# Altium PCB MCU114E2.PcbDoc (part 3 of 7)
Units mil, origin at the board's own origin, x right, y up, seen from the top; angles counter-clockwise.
Board outline 4153.94 x 2313.28 mil, 8 copper layers (Top Layer, GND 2, Signal Layer 3, Power 4, Power 5, Signal Layer 6, GND 7, Bottom), stack 61.2 mil thick; 444 components, 418 nets, 1811 pads, 981 vias.
Unrouted connection lines stored in the file: 3.
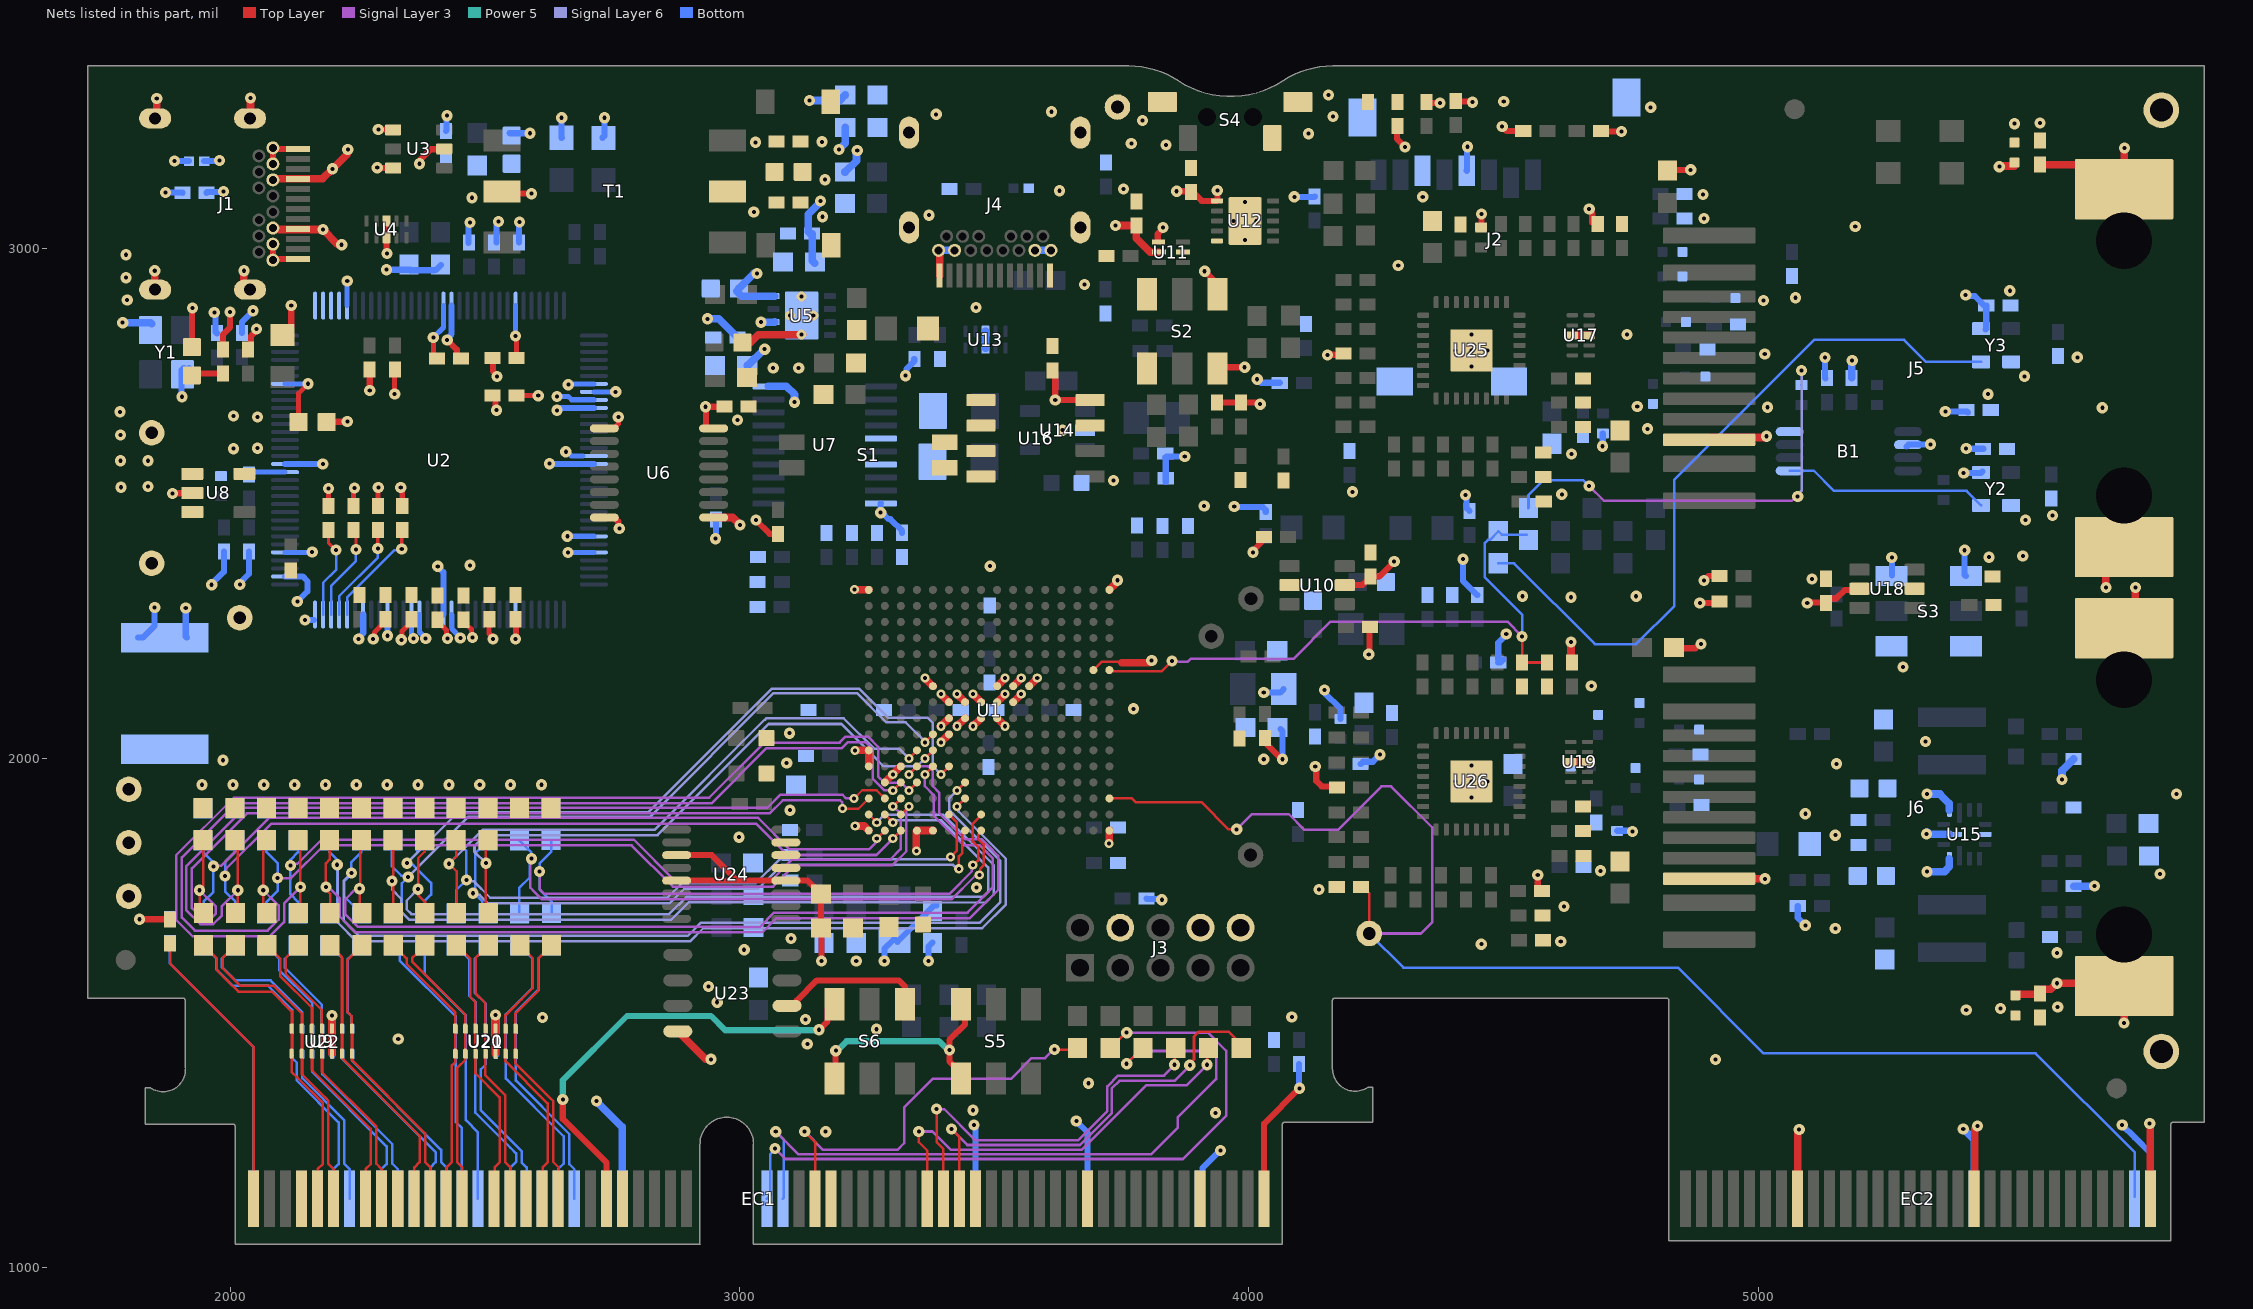
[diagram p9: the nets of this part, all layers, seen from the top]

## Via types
v1: diameter 22, hole 8, Top Layer to Bottom, tented both sides, 810 vias
v2: diameter 18, hole 8, Top Layer to Bottom, tented both sides, 153 vias
v3: diameter 19.68, hole 7.87, Top Layer to Bottom, tented both sides, 10 vias
v4: diameter 19.68, hole 7.87, Top Layer to Bottom, tented bottom, 4 vias
v5: diameter 19.68, hole 7.87, Top Layer to Bottom, tented top, 4 vias

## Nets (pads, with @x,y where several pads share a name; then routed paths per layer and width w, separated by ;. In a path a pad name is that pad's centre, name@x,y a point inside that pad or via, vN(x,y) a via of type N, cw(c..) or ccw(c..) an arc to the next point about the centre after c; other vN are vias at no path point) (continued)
3V3: B1.6 C31.1 C35.1 C36.1 C37.1 C40.2 C43.1 C64.1 C66.1 C86.2 C103.1 C152.1 C153.1 EC1.119 J2.4 J3.10 L3.1 L4.1 R1.2 R2.2 R34.1 R35.1 R36.2 R37.2 R39.2 R40.2 R42.2 R46.1 R51.2 R54.2 R61.2 R71.1 R73.1 R88.2 R89.2 R100.2 R105.2 R106.2 R107.2 R108.1 R111.2 R130.2 R131.1 R133.2 R134.2 R137.2 R138.1 R142.1 R145.2 R151.2 R166.1 R168.2 R202.2 R204.2 R205.1 S2.1 S2.4 S3.1 S3.4 TP5.1 U6.16 U7.20 U10.5 U11.1 U12.1 U16.8 U18.5 Y2.4 Y3.4 | length 3402.1
  Top Layer w12: v1(1822,1684) 1822.06,1683.94 1876.19,1683.94 R204.2@1876.19,1683.88 ; v1(2933.02,2690) C31.1@2969.4,2690 ; v1@2934,2692 2934,2649.29 2935.73,2647.56 U6.16@2949.09,2647.56 ; v1(3032.27,2467.37) 3059.26,2440.38 R100.2@3075,2440.38 ; C86.2@3614,2761.57 3619.6,2755.96 v1(3619.6,2703.23) 3676.33,2703.23 U16.8@3679.87,2699.69 ; U11.1@3820.83,3014.5 3820.83,3029.13 3831,3039.29 v1(3831,3042) ; v1(3858,3113) 3888.38,3113 3907.32,3094.06 U12.1@3937.32,3094.06 3937.83,3094.57 v1(3937.83,3114.27) ; v1(3913,2956) 3937.9,2931.1 S2.1@3937.9,2910.83 ; R54.2@3936.87,2698.31 R51.2@3983.87,2698.31 4018.69,2698.31 v1(4022,2695) v1@4023.31,2696.31 ; S2.4@3937.9,2765.17 3940.23,2767.5 v1(3991.48,2767.5) ; v1(4007.83,2404.27) 4007.83,2407.27 R39.2@4029.25,2428.69 ; EC1.119@4029.8,1135.27 4029.8,1282.8 v1(4099,1352) ; R46.1@4031,2039.38 4031,2031 v1@4062,2000 ; v1(4130,1984) 4131.91,1982.09 4131.91,1955.37 4142.6,1944.68 4172.26,1944.68 R142.1@4172.26,1942.8 ; v1(4153.83,2791.27) 4154.54,2791.98 4183.58,2791.98 R108.1@4184.29,2791.27 ; U10.5@4188.01,2339.69 4221.87,2339.69 C37.1@4238.83,2356.65 4255.65,2356.65 v1(4285,2386) ; v1(4235,2204) 4236.45,2205.45 4236.45,2256.55 R40.2@4237.9,2258 ; C36.1@4290.4,3240.27 4290.4,3215.92 v1(4306.5,3199.82) ; R36.2@4348.51,3288.31 4350.55,3286.27 v1(4374.83,3286.27) ; R37.2@4406.83,3290.27 4408.23,3288.87 4437.77,3288.87 v1(4438.79,3287.85) ; R134.2@4455.83,3041.95 4456.67,3042.8 v1(4456.67,3068.27) ; v1(4497,3240) 4506,3231 R111.2@4538.38,3231 ; v1(4566.87,1770.69) 4566.87,1742.69 R151.2@4571.87,1737.69 ; v1(4667.83,3078.27) 4667.83,3075.56 4673.82,3069.57 4673.82,3051.9 R107.2@4677.83,3047.89 ; R89.2@4690.62,3231 4691.62,3230 v1(4731,3230) ; v1(4885,2305) 4920.57,2305 R138.1@4923.25,2307.69 ; v1(4893.28,2349.13) 4901.62,2357.48 R137.2@4923.6,2357.48 ; v1(5095.87,2304.69) 5096.87,2305.69 C103.1@5131.87,2305.69 ; C103.1@5132.44,2305.06 5132.44,2307.85 5138.25,2313.66 5152.85,2313.66 5169.2,2330.01 5196.2,2330.01 U18.5@5199.87,2333.69
  Bottom w12: v1(1822,1684) 1822.28,1684.28 1881.37,1684.28 R205.1@1881.64,1684.55 ; v1(2953,2431) 2953.56,2431.56 2953.56,2468.4 R1.2@2954.11,2468.95 ; U7.20@3277.24,2499.84 3277.09,2499.84 3277,2499.75 v1(3277,2482) 3279.71,2482 3292.37,2469.34 3296.22,2469.34 3319,2446.56 C35.1@3319,2442.62 ; v1(3284.17,1601.73) 3284.17,1626 3303.17,1645 L4.1@3304,1645 ; L4.1@3309.83,1639.27 3381.33,1710.76 C66.1@3386.53,1710.76 ; v1(3326,2751) 3327.91,2752.91 3327.91,2764.35 3343,2779.44 R71.1@3343,2783.38 ; R202.2@3798.49,1724.69 3799.7,1723.48 3827.62,1723.48 v1(3828.83,1722.27) ; R105.2@3836.62,2542 3836.62,2589 3835.62,2590 3837.82,2592.2 v1(3873.9,2592.2) ; v1(3971.06,2494) 3972.18,2492.88 4027.06,2492.88 4032.87,2487.07 R34.1@4032.87,2483.31 ; v1(4016,2744) 4016.75,2744 4023.75,2737 R88.2@4060.38,2737 ; v1(4029,2129) 4061.19,2129 L3.1@4067.87,2135.69 ; C64.1@4061.48,2057.54 4065.88,2053.14 v1(4065.88,1998) ; v1(4089,3102) 4128.38,3102 R61.2@4129,3102.62 ; R42.2@4098,1399.38 4098.5,1398.88 4098.5,1352.5 v1(4099,1352) ; v1(4148,2134) 4148,2129 4179.99,2097.01 R168.2@4179.99,2077.06 ; R130.2@4218.98,1988.33 4223.82,1993.16 4243.16,1993.16 v1(4257,2007) ; v1(4420.03,2390.69) 4420.03,2348.31 R145.2@4448.03,2320.31 ; v1(4425,2517) 4425,2514.29 4427.06,2512.23 4427.06,2491.12 R35.1@4432.87,2485.31 ; J2.4@4427.45,3153.27 4428.14,3153.96 4428.14,3199.58 v1(4428.83,3200.27) ; R133.2@4489.3,2187.89 4493.24,2187.89 4499.05,2193.7 4489.3,2193.7 4489.3,2226.59 4505,2242.29 v1(4505,2243.65) ; v1(4694.01,2612.38) 4694.42,2612.79 4694.42,2637.17 R131.1@4694.83,2637.58 ; R166.1@4722.83,1857.58 4751.52,1857.58 v1(4752.83,1856.27) ; R2.2@5077.15,1709.69 5077.15,1686.85 v1(5092,1672) ; v1(5130.87,2786.69) 5130.87,2746.69 R73.1@5131.87,2745.69 ; S3.4@5261.83,2358.64 v1(5261.83,2394.27) ; B1.6@5290.87,2611.69 5295.06,2615.87 5337.44,2615.87 v1(5337.83,2616.27) ; v1(5366.87,2680.69) 5408.87,2680.69 C43.1@5410.87,2678.69 ; v1(5402.87,2559.69) 5436.87,2559.69 Y2.4@5439.87,2562.69 ; v1(5404.83,2408.27) 5404.83,2360.02 S3.1@5407.27,2357.58 ; v1(5406.83,2909.27) 5408.74,2907.36 5424.58,2907.36 5443.25,2888.69 C153.1@5447.19,2888.69 ; v1(5407.83,2608.27) 5408.62,2607.48 5441.66,2607.48 C152.1@5441.87,2607.69 ; Y3.4@5445.87,2841.69 5447.19,2843 C153.1@5447.19,2887.69
5V0: C51.1 C53.2 C54.2 R20.1 R21.2 R28.1 R29.1 R53.2 R93.2 R99.2 R103.2 TP9.1 U11.2 U15.7 U15.11 | length 291.7
  Top Layer w15: v1@3738,3045.38 v1(3738,3046) 3738.25,3045.75 C51.1@3778.81,3045.75 3778.81,3020.93 3806.47,2993.27 U11.2@3823.17,2993.27
  Bottom w15: v1(5330.83,1777.27) 5365.27,1777.27 5374.91,1786.91 U15.7@5374.91,1802.95 ; v1(5330.83,1929.69) 5356.31,1929.69 5374.91,1911.09 U15.11@5374.91,1898.42 ; R103.2@5618.62,1749 v1(5659.62,1749)
  other v1: 5820.44,1929.69 3066,2766 3116,2766 3769,3207
20MHZ_CLK: R70.1 Y3.3 | length 1424.1
  Bottom w5.2: R70.1@4489.25,2382.72 4520.28,2382.72 4679,2224 4760,2224 4834.83,2298.83 4834.83,2546.83 5109.27,2821.27 5285.83,2821.27 5328.89,2778.21 Y3.3@5437.07,2778.21
25MHZ_CLK: B1.1 Y2.3 | length 404
  Bottom w5: B1.1@5061.29,2564.3 5108.8,2564.3 5148.33,2524.77 5408.51,2524.77 Y2.3@5437.07,2496.21
ADC_3V0_REF: S6.6 U23.6 | length 291.1
  Top Layer w12: U23.6@3093.28,1514 3106.87,1514 3112.24,1519.37 3112.24,1524.24 3151.84,1563.84 3312.51,1563.84 3324.36,1551.99 S6.6@3324.36,1520.35
ADC_REF: C123.1 R57.2 U24.3 U24.5 U24.12 | length 559.3
  Top Layer w12: U24.5@2876.55,1759.77 2995.83,1759.77 ; U24.3@2876.55,1809.77 2945.83,1809.77 2995.83,1759.77 ; C123.1@3159.5,1668.41 3161,1666.91 v1(3161,1601.73) ; C123.1@3159.98,1668.41 R57.2@3159.98,1722.99 ; R57.2@3162.1,1731.22 3133.55,1759.77 U24.12@3091.11,1759.77 2995.83,1759.77
DEBUG_ID4: R3.1 U2.63 | length 183.1
  Top Layer w6.25: R3.1@2192.85,2448.01 2192.85,2422.89 2207.05,2408.69 v1(2207.87,2408.69)
  Bottom w5: U2.63@2182.5,2282.11 2182.5,2344.5 2207.87,2369.87 v1(2207.87,2408.69)
DEBUG_ID5: R4.1 U2.62 | length 188.2
  Top Layer w6.25: R4.1@2241.87,2448.06 2246.87,2443.06 v1(2246.87,2409.69)
  Bottom w5: U2.62@2198.25,2282.11 2198.25,2338.25 2246.87,2386.87 v1(2246.87,2409.69)
DEBUG_ID6: R5.1 U2.61 | length 197.4
  Top Layer w6.25: v1(2289.87,2411.69) R5.1@2289.87,2448.06
  Bottom w5: U2.61@2214,2282.11 2214,2318 2289.87,2393.87 v1(2289.87,2411.69)
DEBUG_ID7: R6.1 U2.60 | length 217.9
  Top Layer w6.25: v1(2336.87,2410.69) 2336.87,2447.06 R6.1@2337.87,2448.06
  Bottom w5: U2.60@2229.74,2282.11 2229.74,2315.74 2322.7,2408.7 2334.88,2408.7 v1(2336.87,2410.69)
EMU_0: EC1.2 R205.2 | length 567
  Bottom w5: R205.2@1881.64,1637.31 1881.64,1597.36 2046.62,1432.38 EC1.2@2046.62,1138.69
EMU_1: EC1.1 R204.1 | length 566.1
  Top Layer w5: R204.1@1882,1636.63 1882,1597 2046.62,1432.38 2046.62,1282.29 EC1.1@2046.62,1138.69
EMU_3V3: C2.1 C3.1 C4.1 C5.1 C6.1 C7.1 C8.1 C9.1 C18.2 C30.1 R3.2 R4.2 R5.2 R6.2 R7.1 R10.2 R13.2 R14.1 TP2.1 U2.7 U2.8 U2.9 U2.16 U2.26 U2.28 U2.39 U2.47 U2.51 U2.52 U2.69 U2.79 U2.90 U2.101 U2.113 U2.122 U6.1 U8.5 | length 1635.2
  Top Layer w5: U6.1@2733.52,2648.56 U6.1@2734.52,2647.56
  Top Layer w10: C18.2@2134.44,2660 2134.44,2716.41 v1(2153.09,2735.07) ; R3.2@2192.85,2495.26 v1(2192.87,2529.69) ; R4.2@2241.87,2495.31 2241.87,2528.69 v1(2243.87,2530.69) ; v1(2280.83,2234.27) 2283.13,2236.56 2283.13,2246.92 2305.09,2268.89 C7.1@2305.09,2272.82 ; R5.2@2289.87,2495.31 2289.87,2530.69 v1(2290.87,2531.69) ; v1(2323,2715) 2323,2762.06 R7.1@2324,2763.06 ; v1(2334.87,2531.69) 2337.87,2528.69 R6.2@2337.87,2495.31 ; v1(2335.98,2232.42) 2337.13,2233.56 2337.13,2249.33 2349.06,2261.27 2349.48,2261.27 2357.09,2268.89 C6.1@2357.09,2272.82 ; v1(2398.87,2825.69) 2398.87,2792.06 C9.1@2406.25,2784.69 ; C5.1@2408.09,2271.82 2408.09,2267.89 2424.54,2251.44 2424.54,2237.56 v1(2426.83,2235.27) ; C4.1@2459.09,2271.82 2459.09,2267.89 2473.54,2253.44 2473.54,2239.56 v1(2475.83,2237.27) ; C3.1@2508.09,2272.82 2508.09,2244.72 2519.09,2233.72 v1@2519.09,2233.07 ; v1(2559.87,2828.69) 2562.49,2826.06 C8.1@2562.49,2785.69 C8.1@2563.25,2786.44 ; C30.1@2560.87,2711.69 v1(2604.87,2711.69) ; U6.1@2733.52,2648.56 2754.64,2648.56 2762,2655.92 v1(2762,2670)
  Top Layer w12: R14.1@2034.87,2802.31 2040.68,2808.12 2040.68,2828.79 2051.87,2839.98 v1(2051.87,2842.69) ; C2.1@2560.09,2272.82 2561.09,2271.82 v1@2561.09,2234.44
  Bottom w10: R10.2@2036.87,2557.31 2041.2,2561.64 U2.79@2107.7,2561.64 ; U2.69@2107.7,2404.16 2160.18,2404.16 v1(2161.09,2405.07) ; U2.90@2107.7,2734.86 2107.8,2734.97 2152.99,2734.97 v1(2153.09,2735.07) ; U2.101@2229.74,2888.41 2229.74,2936.56 v1(2229.87,2936.69) ; U2.52@2355.73,2282.11 2355.73,2239.37 v1(2359.83,2235.27) ; U2.51@2371.48,2282.11 2371.48,2247.62 v1(2383.83,2235.27) ; v1@2397.87,2824.69 v1(2398.87,2825.69) 2418.72,2845.53 U2.113@2418.72,2888.41 ; U2.47@2434.47,2282.11 2435.53,2281.05 2435.53,2253.46 2451.83,2237.16 v1(2451.83,2236.27) ; v1(2559.87,2828.69) 2560.45,2829.27 U2.122@2560.45,2888.41 ; v1@2560.09,2233.07 2560.45,2233.42 U2.39@2560.45,2282.11 ; v1(2641.85,2710.32) 2663.7,2710.32 2670.4,2703.62 2714,2703.62 U2.9@2714,2703.37 ; v1(2658.87,2601.69) 2661.58,2601.69 2669.94,2593.32 U2.16@2692.44,2593.32 ; v1(2661.87,2435.69) U2.26@2713.98,2435.67 ; v1(2663,2404) 2663.08,2404.08 2713.92,2404.08 U2.28@2714,2404.16 ; v1(2663.83,2733.27) 2665.43,2734.86 U2.7@2714,2734.86 ; U2.8@2714,2719.12 2714.07,2719.19 2756.76,2719.19 v1(2756.83,2719.27)
  other v1: 2516.09,2234.07 2560.09,2234.07 2006.87,2607.69 2053.87,2608.69 2053.87,2669.69 2006.87,2671.69
EMU_5V0: C16.1 C17.2 C20.1 C21.1 C22.1 J1.A4 J1.A9 J1.B4 J1.B9 R15.2 R18.2 T1.5 TP1.1 U3.2 U8.1 U8.3 | length 577.7
  Top Layer w12: TP1.1@1845.87,2638.69 TP1.1@1848.81,2641.62 ; C17.2@1929.81,2759.13 1929.81,2755.06 C16.1@1985.87,2755.06 ; v1(2201,3157) v1@2202,3158 ; v1@2368.86,3170.17 2372,3170.17 2373.36,3171.53 2373.36,3174.67 2394.08,3195.39 2419.61,3195.39 U3.2@2420.29,3196.07 ; T1.5@2533.61,3112.69 2538.03,3108.27 v1(2591.83,3108.27)
  Top Layer w15: J1.B4@2083.93,3040.76 2086.53,3038.16 2096.14,3038.16 2096.29,3038 v1(2182,3038) 2210.66,3009.34 2217.66,3009.34 v1(2219,3008) ; J1.B9@2083.93,3135.24 2085.9,3137.21 J1.A4@2133.54,3137.21 2181.21,3137.21 v1(2201,3157) ; v1@2202,3158 2229.66,3185.66 2229.66,3193.66 v1(2231,3195)
  Bottom w12: C20.1@1949.09,3172.07 1949.7,3172.67 1978.23,3172.67 v1(1978.83,3173.27) ; R15.2@1953.72,3110.07 1954.82,3111.17 1985.73,3111.17 v1(1986.83,3112.27)
  other v1: 1786,2532 1838.87,2533.35 1784.87,2584.02 1838.87,2584.02 1784.87,2634.69 1784,2680 1797.83,2899.27 1795.83,2943.27 1795.83,2988.27 2474.83,3100.27 2371.45,3166.91
EMU_GND: C1.2 C2.2 C3.2 C4.2 C5.2 C6.2 C7.2 C8.2 C9.2 C10.2 C11.2 C12.2 C13.2 C14.2 C15.2 C16.2 C17.1 C18.1 C19.2 C20.2 C21.2 C22.2 C30.2 C34.2 D1.1 D5.2 D6.2 J1.A1 J1.A12 J1.B1 J1.B12 J1.M1 J1.M2 J1.S1 J1.S2 J1.S3 J1.S4 R11.1 R12.1 R15.1 R16.1 R17.2 TP3.1 U2.10 U2.17 U2.48 U2.55 U2.58 U2.64 U2.66 U2.80 U2.114 U3.4 U3.6 U4.3@2306.85,3021.82 U4.8@2306.85,3054.7 U6.8 U8.2 Y1.2 Y1.4 | length 2560.7
  Top Layer w12: v1(1886.87,2519.69) 1887.37,2520.19 1925.37,2520.19 U8.2@1926.87,2521.69 ; C17.1@1924.81,2810.79 1924.81,2878.67 v1@1926.13,2879.99 ; C16.2@1985.87,2802.31 1985.87,2831.69 2000,2845.81 v1(2000,2876) ; J1.M1@2083.93,3009.26 J1.B1@2083.93,2977.76 2085.9,2979.73 J1.A12@2133.54,2979.73 ; J1.M2@2083.93,3166.74 J1.B12@2083.93,3198.24 2085.9,3196.27 J1.A1@2133.54,3196.27 ; D1.1@2102.87,2831.02 2104.35,2831.02 2120,2846.68 v1(2120,2889) ; C18.1@2189.56,2660 2190.06,2660.5 2229.5,2660.5 v1(2230,2661) ; v1@2273.87,2722.13 v1(2274,2722) 2274,2762.94 C1.2@2273.87,2763.06 ; v1(2288.83,3159.27) 2289.13,3158.97 2319.6,3158.97 U3.6@2319.9,3158.66 ; v1(2290.83,3234.27) 2291.23,3233.87 2319.5,3233.87 U3.4@2319.9,3233.47 ; U4.8@2306.85,3054.7 U4.3@2306.85,3021.82 2306.85,2992.31 v1(2308.09,2991.07) ; v1(2426,2821) 2445.15,2801.85 2445.15,2790.5 2450.97,2784.69 C9.2@2453.49,2784.69 ; C30.2@2515.25,2713.69 2520.92,2708.02 2520.92,2685.18 v1(2522.83,2683.27) ; C8.2@2515.25,2785.69 2515.87,2785.06 2515.87,2759.93 2523.83,2751.97 v1(2523.83,2749.27) ; U6.8@2734.52,2472.56 2754.18,2472.56 2762.09,2464.65 2762.09,2452.91 v1(2764,2451)
  Top Layer w15: v1(1852,2957) 1852,2920.72 J1.S3@1852.83,2919.89 ; J1.S2@1852.83,3256.11 1856,3259.28 v1(1856,3295) ; v1(2027,2957) 2027,2931.94 J1.S4@2039.05,2919.89 ; J1.S1@2039.05,3256.11 2040,3257.06 v1(2040,3296)
  Bottom w12: C34.2@1818.87,2236.69 1828.87,2236.69 1851.87,2259.69 v1(1851.87,2295.69) ; v1(1872.83,3110.27) 1872.93,3110.17 1906.37,3110.17 R15.1@1906.47,3110.07 ; v1(1890.83,3172.27) 1890.93,3172.17 1919.19,3172.17 C20.2@1919.29,3172.07 ; v1@1904.64,2719.27 1904.64,2762.08 Y1.4@1908.83,2766.27 ; v1(1912.87,2294.69) 1912.87,2238.69 C34.2@1914.87,2236.69 ; Y1.4@1914.04,2761.05 Y1.4@1919.37,2766.38 ; v1(1963.82,2340.57) 1963.82,2342.07 1987.82,2366.07 C15.2@1987.82,2405.95 ; v1(1969,2875) 1970.91,2873.09 1970.91,2837.27 C14.2@1973.87,2834.31 ; v1(2019.05,2341.23) 2019.05,2343.93 2037.05,2361.93 R11.1@2037.05,2405.98 ; C13.2@2023,2834.62 2023,2856.19 v1(2045.13,2878.31) ; U2.66@2107.7,2356.91 2142.19,2356.91 2151.83,2347.27 2151.83,2327.64 v1(2131.87,2307.69) ; U2.80@2107.7,2577.38 2181.57,2577.38 v1(2181.87,2577.69) ; v1(2146.83,2271.27) U2.64@2164.69,2271.27 ; v1(2252.33,2234.07) 2252.33,2236.88 2261.24,2245.78 U2.58@2261.24,2282.11 ; v1(2307,2959) R16.1@2354.09,2959 ; U2.55@2308.48,2282.11 2308.66,2281.94 v1(2308.66,2240.44) ; R16.1@2353.09,2958 R17.2@2400.5,2958 ; R16.1@2353.09,2958.07 2403.59,2958.07 R17.2@2414.09,2968.57 ; v1(2407.53,2376.69) 2418.72,2365.5 U2.48@2418.72,2282.11 ; C22.2@2423.63,3231.17 2424.73,3232.28 2424.73,3260.17 v1(2425.83,3261.27) ; v1(2426,2821) 2426,2823.71 2434.73,2832.44 2434.73,2888.14 U2.114@2434.47,2888.41 ; C11.2@2468.09,3011.69 2468.09,3048.91 v1(2470.87,3051.69) ; C12.2@2523.02,3012.62 2523.02,3049.84 v1(2526.8,3053.62) ; C21.2@2548.76,3227.44 2549.43,3226.77 v1(2588.5,3226.77) ; C10.2@2567,3012.62 2567,3051.84 v1(2567.78,3052.62) ; v1(2626.83,2578.27) 2627.27,2577.83 2713.55,2577.83 U2.17@2714,2577.38 ; v1(2641.35,2683) 2642.71,2683 2647.33,2687.62 U2.10@2714,2687.62 ; D5.2@2650.87,3218.02 2650.83,3218.07 v1(2650.83,3257.27) ; D6.2@2730.87,3218.02 2734.83,3221.98 v1(2734.83,3257.27)
  Bottom w15: v1(1789,2855) 1843.72,2855 Y1.2@1845.84,2852.88
  other v1: 2470.87,2378.69 1905.27,2709.64 1926.13,2883.99
ERRORSTS: EC2.178 R38.2 TP11.1 U1.P16 | length 2942.4
  Top Layer w5: U1.P16@3726.04,1921.06 3770.21,1921.06 3777.34,1913.94 3878.79,1913.94 3878.96,1913.77 3906.48,1913.77 3959.74,1860.52 v1(3975.88,1860.52) ; R38.2@4218.95,1752.27 4218.95,1751.76 4232.75,1737.96 4233.07,1737.96 4236,1735.03 TP11.1@4236,1656
  Signal Layer 3 w5: v1(3975.88,1860.52) 4005.63,1890.27 4078.04,1890.27 4108.3,1860 4175.29,1860 4260.06,1944.77 4279.08,1944.77 4359.3,1864.55 4359.3,1677.73 4337.56,1656 TP11.1@4236,1656
  Bottom w5: TP11.1@4236,1656 4303,1589 4842.01,1589 5010.25,1420.77 5544.23,1420.77 5739.14,1225.86 EC2.178@5739.14,1138.98
ETH1_EARTH: C101.2 C117.2 J5.10 J5.13 J5.14 J6.10 J6.13 J6.14 pad.6 R136.2 R170.2 | length 938.3
  Top Layer w15: J6.10@4903.31,1763.48 5012.62,1763.48 v1(5012.83,1763.27) ; J5.10@4903.31,2625.13 4907.81,2629.64 5011.75,2629.64 5014.11,2632 v1(5016,2632) ; v1(5472.83,3161.27) 5474.17,3162.61 5501.98,3162.61 C101.2@5504.44,3165.06 ; C117.2@5504.44,1534.69 5506.4,1536.65 5550.47,1536.65 R170.2@5552.44,1538.62 5552.44,1542.56 5556.75,1546.87 5573.54,1546.87 v1@5584.94,1558.27 ; R136.2@5552.44,3165.06 J5.13@5669.68,3165.06 ; v1(5585.83,1558.27) v1@5584.94,1558.27 ; v1(5682,2335) 5682,2378.63 J5.14@5717.87,2414.5 ; v1(5717.83,1480.27) 5717.83,1548.07 5707.64,1558.27 v1@5584.94,1558.27 ; J6.13@5717.87,2255.21 5740,2277.34 v1(5740,2335) ; J5.13@5717.87,3116.87 5718.44,3117.43 v1(5718.44,3197.69)
F28P65x_25MHZ_CLK: R65.2 R75.2 | length 865.8
  Signal Layer 3 w5: v1(4667.83,2534.27) 4696.65,2505.45 5065.57,2505.45 5074.12,2514 v1(5077,2514)
  Signal Layer 6 w5: v1(5077,2514) 5077,2517.6 5084.83,2525.43 v1(5084.83,2761.27)
  Bottom w5.2: R75.2@4548.44,2491.17 4548.56,2491.29 4548.56,2516.56 4578,2546 4656.1,2546 v1(4667.83,2534.27) ; R65.2@5084.44,2732.53 5084.83,2732.92 v1(5084.83,2761.27)
F28P65x_CLK: C126.2 R41.2 R70.2 R75.1 U1.F16 | length 1274
  Top Layer w5: U1.F16@3726.04,2173.03 3728.1,2170.97 3828.97,2170.97 v1(3849,2191) ; v1(4536,2239) C126.2@4536,2187.62 4536.27,2187.89 R41.2@4585,2187.89
  Signal Layer 3 w5: v1(3849,2191) 3850.23,2189.77 3880.08,2189.77 3885.48,2195.17 4087.25,2195.17 4160.09,2268 4507,2268 v1(4536,2239)
  Bottom w5: v1(4536,2239) 4536,2282 4463.05,2354.95 4463.05,2422.67 4468.91,2428.53 4473.05,2428.53 4489.25,2444.73 R70.2@4489.25,2445.72 4496.2,2438.77 R75.1@4545.62,2438.77
GND: B1.4 C23.2 C24.1 C25.2 C26.1 C27.2 C28.1 C29.2 C31.2 C32.2 C33.2 C34.1 C35.2 C36.2 C37.2 C38.2 C39.2 C40.1 C41.1 C42.1 C43.2 C44.2 C45.1 C46.2 C47.2 C49.2 C51.2 C52.1 C53.1 C54.1 C55.2 C56.2 C57.2 C58.2 C59.2 C60.2 C61.2 C62.2 C63.1 C64.2 C65.2 C66.2 C67.2 C68.2 C69.2 C70.2 C71.2 C72.2 C73.2 C74.2 C75.2 C76.2 C77.2 C78.2 C79.2 C80.2 C81.2 C82.2 C83.2 C84.1 C85.1 C86.1 C87.1 C88.1 C89.2 C90.2 C91.2 C92.2 C93.2 C94.2 C95.1 C96.1 C97.2 C98.2 C99.2 C100.2 C101.1 C102.1 C103.2 C104.1 C105.2 C106.2 C107.2 C108.2 C109.2 C110.2 C111.1 C112.1 C113.2 C114.1 C115.2 C116.1 C117.1 C118.1 C119.1 C120.2 C121.2 C122.2 C123.2 C124.2 C125.2 C126.1 C128.2 C129.2 C130.2 C131.2 C132.2 C133.2 C134.2 C135.2 C136.2 C137.2 C138.2 C139.2 C140.2 C141.2 C142.2 C143.2 C144.2 C145.2 C146.2 C147.2 C148.2 C149.2 C150.2 C151.2 C152.2 C153.2 D2.1 D7.1 EC1.7 EC1.10 EC1.19 EC1.22 EC1.35 EC1.38 EC1.46 EC1.47 EC1.65 EC1.83 EC1.97 EC1.111 EC2.135 EC2.157 EC2.179 J2.6 J2.S1 J2.S2 J2.S3 J2.S4 J3.4 J3.8 J4.A1 J4.A12 J4.B1 J4.B12 J4.M1 J4.M2 J4.S1 J4.S2 J4.S3 J4.S4 R22.1 R23.1 R25.1 R26.1 R27.1 R31.1 R32.2 R38.1 R41.1 R43.1 R48.1 R69.2 R72.1 R74.2 R76.2 R77.1 R95.1 R104.1 R109.1 R112.1 R113.1 R123.1 R124.1 R125.1 R127.1 R128.1 R129.1 R132.1 R135.1 R136.1 R139.2 R140.2 R141.2 R143.1 R146.1 R147.1 R159.1 R160.1 R161.1 R162.1 R163.2 R167.1 R169.1 R170.1 R171.1 R206.1 S1.3 S1.4 S2.3 S2.6 S3.3 S3.6 S4.1 S4.2 S4.3 T1.2 TP8.1 U1.A1 U1.A16 U1.F15 U1.G5 U1.G9 U1.G10 U1.G11 U1.H6 U1.H7 U1.H8 U1.H9 U1.H10 U1.J6 U1.J7 U1.J8 U1.J9 U1.K6 U1.L1 U1.M1 U1.M3 U1.N2 U1.T1 U1.T4 U1.T5 U1.T16 U5.5 U5.9@3122,2868.8 U6.9 U7.10 U7.15 U7.17 U9.5 U9.10 U10.2 U11.5 U12.5 U12.11 U13.3@3482.69,2805.13 U13.8@3482.69,2838 U14.2 U15.2 U15.9 U16.1 U16.2 U16.3 U16.4 U16.7 U17.3@4634.86,2830.21 U17.8@4667.74,2830.21 U18.2 U19.3@4631.55,1992.82 U19.8@4664.42,1992.82 U20.5 U20.10 U21.5 U21.10 U22.5 U22.10 U23.4 U24.13 U24.14 U24.15 U25.33 U26.33 Y2.2 Y3.2 | length 2327.2
  Top Layer w5: U1.F15@3694.54,2173.03 3710.52,2189 3750.17,2189 3751.63,2190.46
  Top Layer w12: R135.1@4821.39,3153.32 4823.07,3155 v1(4867,3155) ; R169.1@4834.33,2217.27 4835.6,2216 4876.29,2216 4884.29,2224 v1(4887,2224)
  Top Layer w15: U9.5@2199.56,1420.08 U9.10@2199.56,1469.29 ; U9.10@2200,1469.29 v1(2200,1495) ; U20.5@2520.56,1420.08 2520.56,1453 2521,1453.44 v1(2521,1496) ; U23.4@2878.72,1464 2933.72,1409 v1(2944,1409) ; U6.9@2949.09,2472.56 2986.44,2472.56 v1(3001,2458) ; C26.1@3014.5,2809 3037.09,2831.6 v5@3124,2831.6 ; v2(3225.5,2330.98) 3225.83,2330.65 3253.46,2330.65 U1.A1@3253.6,2330.51 ; v2(3226.84,2015.32) 3227.07,2015.55 U1.L1@3253.6,2015.55 U1.M1@3253.6,1984.05 ; v2(3227,1867) 3244.66,1867 U1.T1@3253.6,1858.07 ; U1.N2@3285.09,1952.55 v2(3300.84,1968.3) U1.M3@3316.59,1984.05 ; v2(3347,1818) 3347,1856.98 U1.T4@3348.09,1858.07 U1.T5@3379.58,1858.07 ; v2(3363.83,2157.28) U1.G5@3379.58,2141.53 ; J4.B1@3390.76,2997.07 3392.73,2995.1 J4.A12@3392.73,2947.46 ; v2@3394.16,2062.6 3395.14,2062.6 U1.J6@3411.08,2078.54 ; v2(3395.33,2031.29) U1.K6@3411.08,2047.04 ; v2(3395.33,2125.78) U1.H6@3411.08,2110.03 ; v2@3425.65,2062.6 3426.63,2062.6 U1.J7@3442.57,2078.54 ; v2(3426.83,2125.78) U1.H7@3442.57,2110.03 ; v2@3457.15,2062.6 3458.13,2062.6 U1.J8@3474.07,2078.54 ; v2(3458.32,2125.78) U1.H8@3474.07,2110.03 ; U1.J9@3505.57,2078.54 v2(3521.31,2062.79) ; U1.H9@3505.57,2110.03 v2(3521.31,2125.78) ; U1.G9@3505.57,2141.53 v2(3521.31,2157.28) ; U1.H10@3537.06,2110.03 v2(3552.81,2125.78) ; U1.G10@3537.06,2141.53 v2(3552.81,2157.28) ; U1.G11@3568.56,2141.53 v2(3584.31,2157.28) ; v2(3725.44,1832.95) 3725.44,1857.47 U1.T16@3726.04,1858.07 ; U1.A16@3726.04,2330.51 3726.04,2330.71 3740.32,2344.99 3740.32,2348.06 v1(3741.66,2349.39) ; 3750.17,2187.67 3804.67,2187.67 v1(3809,2192) ; U19.3@4631.55,1992.82 U19.8@4664.42,1992.82 ; v1(4632,2228) 4632,2189.72 R143.1@4633.83,2187.89 ; U17.3@4634.86,2830.21 U17.8@4667.74,2830.21 ; EC2.135@5076.95,1135.27 5076.95,1267.95 v1(5080,1271) ; EC2.157@5423.41,1135.27 5424.54,1136.4 5424.54,1272.54 v1(5430,1278) ; v1(5768,1283) 5768.93,1282.07 5768.93,1136.2 EC2.179@5769.87,1135.27
  Bottom w12: v1@3371,1600 3371,1630.5 C66.2@3379,1638.5
  Bottom w15: v1(2200,1495) 2200,1444.24 2200.62,1443.62 U22.10@2200.62,1419.01 ; v1(2521,1496) 2521,1444.24 2521.62,1443.62 U21.10@2521.62,1419.01 ; U7.10@3056.76,2730.16 3091.84,2730.16 3107.9,2714.1 v1(3107.9,2699) ; J4.B1@3390.76,2997.07 J4.M1@3422.26,2997.07 ; U13.3@3482.69,2805.13 U13.8@3482.69,2838 ; J4.M2@3579.74,2997.07 J4.B12@3611.24,2997.07 ; R74.2@5183,2746.62 5183,2780 v1(5184,2781) ; v1@5330,1855 5331.89,1855 5336.21,1850.69 U15.9@5375.4,1850.69 ; v1(5596,1958) 5596,1975.96 R206.1@5618.44,1998.4
  other v1: 3169,1267 3934,1304 3458,1309 3685,1362 4916,1408.86 3133,1439 2330,1449 3269,1468 3129.31,1487.43 2613,1491 4084,1492 5408,1505.86 5475,1509 5587.44,1511.69 2956,1521 2939,1552 3229,1601.73 3371,1601.73 5586,1618 3009,1624 4456,1635 4612,1640 3101,1646 5151,1666 4618.44,1708.69 4137.44,1742.24 3465,1746 5788.44,1772.69 4690,1779 2999,1845 5151,1849 5329.66,1851.46 5092,1891 3099,1898 1945,1948 2005.55,1948 2066.09,1948 2126.64,1948 2187.18,1948 2247.73,1948 2308.27,1948 2368.82,1948 2429.36,1948 2489.91,1948 2550.45,1948 2611,1948 5153,1989 3092.44,1990.69 1986,1996 4029,1998 5328,2033 3098,2049.25 3773,2097 4672,2142 5284,2179 4632,2316 4537,2318 4760,2318 5105.44,2351.69 3492,2377 5452.44,2394.69 5519,2397 5524.44,2467.69 5577.44,2476.69 3912,2495 4614,2518 4203,2523 3734,2545 4633,2597 3633.84,2644 4782.44,2646.69 2995.81,2663.72 5675,2688 5018,2689 4762.1,2690.64 5450.44,2714.69 5522.44,2749.69 5626,2787 5012.44,2793.69 4742,2832 3464,2885 5010.07,2898.78 5073,2904 5493.44,2917.69 3677,2930 4293,2967 5190,3044 4893.44,3059.69 3163,3063 3372,3066 3028,3072 4341,3102 4891.44,3106.69 3628,3114 3753.44,3117.69 3837,3204 3031,3209 4117,3226 5502.44,3245.69 5552.44,3246.69 3791,3252 4165,3260 3386,3264 3612.34,3269.11 4788.44,3277.69 4500,3289 4156,3302
  other v2: 3395.33,2062.79 3426.83,2062.79 3458.32,2062.79
  other v3: 4436.44,1923.19 4404.94,1954.69 4436.44,1954.69 4467.93,1954.69 4436.44,1986.18 4436.44,2769.19 4404.94,2800.69 4436.44,2800.69 4467.93,2800.69 4436.44,2832.18
  other v4: 3992.44,3017.28 3969.8,3054.69 4015.07,3054.69 3992.44,3092.09
  other v5: 3122,2831.4 3099.36,2868.8 3144.64,2868.8 3122,2906.2
HSEC_5V0: C27.1 C28.2 EC1.48 EC1.84 EC1.98 EC1.112 EC2.158 EC2.180 R22.2 R24.2 R28.2 TP4.1 U5.8 | length 1285.2
  Bottom w12: v1(3460,1280) 3462.87,1277.13 EC1.84@3462.87,1139.75 ; v1@3660.83,1287.83 3683.35,1265.32 EC1.98@3683.35,1135.27 ; EC1.112@3903.82,1135.27 3908.65,1140.09 3908.65,1195.08 v1(3943.83,1230.27) ; v1(5714,1280) 5738.34,1255.66 5769.87,1224.13 EC2.180@5769.87,1139.76
  Bottom w15: v1(2719,1327) 2769.96,1276.04 EC1.48@2769.96,1135.27 ; v1(2937.15,2862.51) 2959.11,2862.51 C27.1@2995.62,2826 ; C28.2@2994.56,2917 3004.37,2907.19 U5.8@3068.88,2907.19 ; C28.2@2998.56,2922 3027.99,2951.44 v1(3034.06,2951.44) ; R22.2@3015.03,2770.95 3016.02,2770.95 3048.09,2803.03 v1(3049.23,2803.03) ; v1(3195,3195) 3207.5,3207.5 R28.2@3207.5,3238 ; R24.2@3206.54,3150.9 3207.52,3150.9 3229.66,3173.04 3229.66,3191.66 v1(3231,3193) ; v1@5401.83,1272.27 5423.41,1250.69 EC2.158@5423.41,1135.27
  other v1: 5402.04,1272.27 3661,1288
HSEC_ADC-VREFHI: EC1.45 S6.4 | length 901.3
  Top Layer w12: v1(2653,1330) 2653,1292 2738.46,1206.54 EC1.45@2738.46,1135.27 ; v1(3156,1467) 3172.88,1483.88 3172.88,1506.66 S6.4@3186.57,1520.35
  Power 5 w12: v1(2653,1330) 2653,1368 2779,1494 2944,1494 2972,1466 3155,1466 v1(3156,1467)
HSEC_ADC_A0A1_N: EC1.11 R173.2 U9.2 U9.13 | length 636.9
  Top Layer w4.9: R173.2@2010.13,1632.95 1985.08,1607.91 1985.08,1588.5 2002.81,1570.78 2020.59,1553 2086.45,1553 2140.5,1498.95 2140.5,1480.29 U9.13@2140.5,1469.29 U9.2@2140.5,1420.08 2140.5,1380.1 2186.34,1334.26 2186.34,1334.19 2189.79,1330.74 2189.79,1330.67 2192.9,1327.56 2192.9,1203.52 2203.03,1193.39 EC1.11@2203.03,1135.27
HSEC_ADC_A0A1_P: EC1.9 R172.2 U9.1 U9.14 | length 637.6
  Top Layer w4.9: R172.2@1948.04,1632.95 1974.18,1606.81 1974.18,1583.99 1977.2,1580.97 1977.2,1580.83 1995.03,1563 1995.17,1563 2016.07,1542.1 2081.94,1542.1 2120.82,1503.22 2120.82,1480.29 2120.82,1384.3 2132.79,1372.32 2132.79,1372.25 2182,1323.04 2182,1203.85 2171.54,1193.39 EC1.9@2171.54,1135.27
HSEC_ADC_A2A3_N: EC1.17 R175.2 U9.4 U9.11 | length 586.1
  Top Layer w4.9: R175.2@2134.31,1632.95 2109.17,1607.82 2109.17,1576.83 2179.87,1506.13 U9.11@2179.87,1469.29 2179.87,1431.08 U9.4@2179.87,1420.08 2179.87,1396.41 2179.87,1384.13 2287,1277 2287,1203.91 2297.52,1193.39 EC1.17@2297.52,1135.27
HSEC_ADC_A2A3_P: EC1.15 R174.2 U9.3 U9.12 | length 586.3
  Top Layer w4.9: R174.2@2072.04,1632.95 2098.27,1606.72 2098.27,1572.31 2160.19,1510.4 2160.19,1388.26 2276,1272.44 2276,1203.36 2266.02,1193.39 EC1.15@2266.02,1135.27
HSEC_ADC_A4A5_N: EC1.23 R177.2 U9.7 U9.8 | length 572.5
  Top Layer w4.9: R177.2@2258.49,1631.97 2230.14,1603.62 2230.14,1501.92 2238.67,1493.39 2238.67,1480.55 2238.93,1480.29 U9.8@2238.93,1469.29 2238.93,1431.08 U9.7@2238.93,1420.08 2238.93,1407.49 2382.9,1263.52 2382.9,1207.03 2393.08,1196.85 EC1.23@2393.08,1138.69
HSEC_ADC_A4A5_P: EC1.21 R176.2 U9.6 U9.9 | length 563
  Top Layer w4.9: R176.2@2196.4,1632.95 2219.24,1610.11 2219.24,1480.29 U9.6@2219.24,1420.08 ; U9.6@2219.24,1411.76 2372,1259 2372,1207.27 2361.58,1196.85 EC1.21@2361.58,1138.69
HSEC_ADC_A8A9_N: EC1.36 R179.2 U21.4 U21.11 | length 555.4
  Bottom w4.9: R179.2@2505.87,1632.33 2505.87,1631.35 2489.62,1615.1 2488.64,1615.1 2480,1606.46 2480,1540 2501.94,1518.06 U21.4@2501.94,1468.22 U21.11@2501.94,1419.01 2501.94,1413.98 2501.94,1399.31 2492.09,1389.46 2492.09,1308.87 2572.31,1228.65 2572.31,1206.55 2582.05,1196.8 EC1.36@2582.05,1138.69
HSEC_ADC_A8A9_P: EC1.34 R178.2 U21.3 U21.12 | length 547.7
  Bottom w4.9: R178.2@2443.78,1632.33 2443.78,1631.35 2469.1,1606.03 2469.1,1533.79 2482.25,1520.64 U21.12@2482.25,1419.01 2481.19,1417.94 2481.19,1304.36 2550.19,1235.36 2561.41,1224.14 2561.41,1207.65 2550.56,1196.8 EC1.34@2550.56,1138.69
HSEC_ADC_A10A11_N: EC1.42 R181.2 U21.7 U21.8 | length 574.1
  Bottom w4.9: R181.2@2631.04,1632.95 2604.4,1606.31 2604.4,1544.95 2560.99,1501.55 U21.7@2560.99,1468.22 U21.8@2560.99,1419.01 2560.99,1367.01 2665.73,1262.27 2665.73,1203.13 2675.47,1193.39 EC1.42@2675.47,1135.27
HSEC_ADC_A10A11_P: EC1.40 R180.2 U21.6 U21.9 | length 580.8
  Bottom w4.9: R180.2@2567.96,1632.33 2593.5,1606.79 2593.5,1549.47 2541.31,1497.28 U21.9@2541.31,1419.01 2541.31,1371.28 2654.83,1257.75 2654.83,1204.24 2643.98,1193.39 EC1.40@2643.98,1135.27
HSEC_ADC_A14B14C14A15B15C15_N: EC1.27 R183.2 U20.2 U20.13 | length 559
  Top Layer w4.9: R183.2@2382.67,1632.95 2382.67,1631.97 2366.42,1615.72 2365.44,1615.72 2357.36,1607.64 2357.36,1601.03 2461.5,1496.89 2461.5,1480.29 2461.5,1431.08 2461.5,1407.95 2446.12,1392.57 2446.12,1206.8 2456.07,1196.85 EC1.27@2456.07,1138.69
HSEC_ADC_A14B14C14A15B15C15_P: EC1.25 R182.2 U20.1 U20.14 | length 552.5
  Top Layer w4.9: R182.2@2320.58,1632.95 2320.58,1631.97 2336.83,1615.72 2337.82,1615.72 2346.46,1607.07 2346.46,1596.51 2442.15,1500.82 2442.15,1480.63 2441.82,1480.29 2441.82,1431.08 2441.82,1403.68 2435.22,1397.08 2435.22,1207.5 2424.57,1196.85 EC1.25@2424.57,1138.69
HSEC_ADC_B0B1_N: EC1.14 R185.2 U22.2 U22.13 | length 653.4
  Bottom w4.9: R185.2@2010.13,1632.95 2010.13,1631.97 1994.43,1616.27 1993.44,1616.27 1983.98,1606.81 1983.98,1590.15 2010.23,1563.9 2079.39,1563.9 2141.57,1501.72 U22.2@2141.57,1468.22 2141.57,1371.96 2223.68,1289.85 2223.68,1204.23 2234.53,1193.39 EC1.14@2234.53,1135.27
HSEC_ADC_B0B1_P: EC1.12 R184.2 U22.1 U22.14 | length 646.8
  Bottom w4.9: R184.2@1948.04,1632.95 1948.04,1631.97 1973.08,1606.92 1973.08,1585.63 2005.71,1553 2074.88,1553 2121.88,1505.99 U22.14@2121.88,1419.01 ; U22.14@2120.82,1412.44 2122.55,1412.44 2123.37,1411.62 2123.37,1409.89 2130.67,1402.59 2130.67,1367.44 2212.78,1285.33 2212.78,1203.13 2203.03,1193.39 EC1.12@2203.03,1135.27
HSEC_ADC_B2B3_N: EC1.20 R187.2 U22.4 U22.11 | length 599.3
  Bottom w4.9: R187.2@2133.33,1632.33 2107.18,1606.18 2107.18,1589.11 2179.87,1516.42 2179.87,1480.29 U22.4@2179.87,1468.22 ; U22.4@2180.94,1468.22 U22.11@2180.94,1419.01 2180.94,1379.83 2318.17,1242.6 2318.17,1204.23 2329.02,1193.39 EC1.20@2329.02,1135.27
HSEC_ADC_B2B3_P: EC1.18 R186.2 U22.3 U22.12 | length 598.9
  Bottom w4.9: R186.2@2071.23,1632.33 2096.28,1607.28 2096.28,1584.6 2161.25,1519.63 U22.12@2161.25,1419.01 2161.25,1384.1 2307.27,1238.08 2307.27,1203.13 2297.52,1193.39 EC1.18@2297.52,1135.27
HSEC_ADC_B4B5_N: EC1.26 R189.2 U22.7 U22.8 | length 585.4
  Bottom w4.9: U22.8@2238.93,1419.01 2238.93,1415.81 2239.99,1414.74 2239.75,1414.5 2239.75,1405.83 2414.28,1231.3 2414.28,1207.1 2424.57,1196.8 EC1.26@2424.57,1138.69 ; U22.7@2238.93,1468.22 2238.93,1480.29 2238.67,1480.55 2238.67,1493.39 2231.21,1500.85 2231.21,1606.03 2240.82,1615.65 2241.81,1615.65 2257.51,1631.35 R189.2@2257.51,1632.33 ; U22.8@2239.99,1419.01 U22.7@2239.99,1468.22
HSEC_ADC_B4B5_P: EC1.24 R188.2 U22.6 U22.9 | length 584.6
  Bottom w4.9: R188.2@2195.42,1632.33 2195.42,1631.35 2211.67,1615.1 2212.65,1615.1 2220.31,1607.44 U22.6@2220.31,1468.22 U22.9@2220.31,1419.01 2220.31,1409.85 2403.38,1226.78 2403.38,1207.1 2393.08,1196.8 EC1.24@2393.08,1138.69
HSEC_ADC_C2C3_N: EC1.33 R191.2 U20.4 U20.11 | length 533.1
  Top Layer w4.9: 2500.87,1431.08 2500.87,1480.29 2500.87,1519.13 2481.86,1538.14 2481.86,1607.96 R191.2@2506.85,1632.95 ; 2500.91,1431.04 2500.91,1377.51 2539.66,1338.76 2539.66,1317.34 2539.76,1317.24 2539.76,1207.65 2550.56,1196.85 EC1.33@2550.56,1138.69
HSEC_ADC_C2C3_P: EC1.31 R190.2 U20.3 U20.12 | length 533.1
  Top Layer w4.9: R190.2@2444.76,1632.95 2470.96,1606.76 2470.96,1533.63 2471,1533.59 2471,1531.89 2481.19,1521.7 2481.19,1480.29 2481.19,1381.81 2528.76,1334.24 2528.76,1206.55 2519.06,1196.85 EC1.31@2519.06,1138.69
HSEC_ADC_C4: EC1.30 R192.2 U21.2 U21.13 | length 540.5
  Bottom w5: R192.2@2381.69,1632.33 2381.69,1576.31 2462.57,1495.43 U21.2@2462.57,1468.22 2462.57,1289.43 2486.5,1265.5 EC1.30@2486.5,1135.27
HSEC_ADC_C6: EC1.28 R193.2 U21.1 U21.14 | length 553.1
  Bottom w5: R193.2@2319.6,1632.33 2332.84,1619.09 2332.84,1603.16 2442.88,1493.12 U21.14@2442.88,1419.01 2442.88,1285.93 2455,1273.82 EC1.28@2455,1135.27
HSEC_ADC_C10C11_N: EC1.39 R195.2 U20.7 U20.8 | length 559
  Top Layer w4.9: R195.2@2631.04,1632.95 2605,1606.92 2605,1544 2559.93,1498.93 2559.93,1480.29 2559.93,1431.08 2559.93,1401.14 2627.73,1333.34 2627.8,1333.34 2634.25,1326.89 2634.25,1207.65 2645.05,1196.85 EC1.39@2645.05,1138.69
HSEC_ADC_C10C11_P: EC1.37 R194.2 U20.6 U20.9 | length 565.5
  Top Layer w4.9: R194.2@2568.95,1632.95 2594.1,1607.8 2594.1,1548.91 2572.35,1527.17 2552.15,1506.96 2540.24,1495.06 2540.24,1480.29 2540.24,1405.41 2623.35,1322.31 2623.35,1206.65 2613.55,1196.85 EC1.37@2613.55,1138.69
HSEC_GPIO11: EC1.63 R96.1 | length 815.1
  Top Layer w5: v1(3127.83,1267.27) 3148.33,1246.77 3148.33,1135.69 EC1.63@3147.91,1135.27 ; v1(3618,1428) 3660.67,1428 R96.1@3663.44,1430.77
  Signal Layer 3 w5: v1(3127.83,1267.27) 3128.08,1267.27 3164.08,1231.27 3309.9,1231.27 3322.83,1244.2 3322.83,1314.73 3378.84,1370.74 3532.87,1370.74 3573.32,1411.19 3599.53,1411.19 3616.35,1428 v1(3618,1428)
HSEC_GPIO12: EC1.58 R45.2 | length 1416.6
  Top Layer w5: R45.2@3727.66,1430.77 3758.16,1461.27 v1(3759.83,1461.27)
  Signal Layer 3 w5: v1(3069.63,1233.76) 3090.12,1213.27 3870.27,1213.27 3955,1298 3955,1425.83 3919.56,1461.27 v1(3759.83,1461.27)
  Bottom w5: EC1.58@3053.43,1135.27 3060,1141.84 3060,1222.33 3069.63,1231.96 v1(3069.63,1233.76)
HSEC_GPIO13: EC1.60 R47.2 | length 1378.1
  Top Layer w5: v1(3759.83,1400.27) 3789.83,1430.27 3789.83,1434.06 R47.2@3791.96,1436.19
  Signal Layer 3 w5: v1(3071,1267) 3115.73,1222.27 3807.58,1222.27 3859.83,1274.52 3859.83,1294.83 3935.33,1370.33 3935.33,1412.77 3922.83,1425.27 3784.83,1425.27 v1(3759.83,1400.27)
  Bottom w5: v1(3071,1267) 3087.13,1250.87 3087.13,1137.48 EC1.60@3084.92,1135.27
HSEC_GPIO25: EC1.77 R98.1 | length 827.6
  Top Layer w5: v1(3351.83,1267.27) 3351.83,1246.17 3368.39,1229.61 EC1.77@3368.39,1135.27 ; v1(3917.83,1398.27) 3917.83,1433.41 R98.1@3920.61,1436.19
  Signal Layer 3 w5: v1(3351.83,1267.27) 3378.73,1267.27 3414.23,1231.77 3671.95,1231.77 3697,1256.82 3797.95,1357.77 3877.33,1357.77 v1(3917.83,1398.27)
HSEC_GPIO26: EC1.79 R50.2 | length 803.3
  Top Layer w5: v1(3386.83,1311.27) 3386.83,1246.3 3399.88,1233.25 EC1.79@3399.88,1135.27 ; R50.2@3849.6,1430.77 R50.2@3853.41,1426.95 ; v1(3853.83,1398.27) 3853.83,1428.36 R50.2@3856.25,1430.77
  Signal Layer 3 w5: v1(3386.83,1311.27) 3401.83,1311.27 3463.33,1249.77 3664.5,1249.77 3722,1307.27 3722,1356 3743,1377 3833.39,1377 3853.83,1397.44 v1(3853.83,1398.27)
HSEC_GPIO27: EC1.81 R56.2 | length 882.4
  Top Layer w5: v1(3415.83,1272.27) 3431.38,1256.72 EC1.81@3431.38,1135.27 ; v1(3883.83,1397.27) 3883.83,1400.47 3892.06,1408.7 3892.06,1453.5 3901.83,1463.27 3959.83,1463.27 3974.44,1448.66 R56.2@3974.44,1436.19
  Signal Layer 3 w5: v1(3415.83,1272.27) 3447.33,1240.77 3668.22,1240.77 3731,1303.54 3731,1352.27 3745.5,1366.77 3853.33,1366.77 v1(3883.83,1397.27)
"Int. V_REF": S5.1 S5.4 S6.1 | length 461
  Top Layer w12: S6.1@3186.57,1374.68 3188.5,1376.61 3188.5,1425.5 v1(3189,1426) ; S5.1@3442.16,1374.68 3412,1404.84 3412,1447 3442.16,1477.16 S5.4@3442.16,1520.35
  Power 5 w12: v1(3189,1426) 3191.71,1426 3210.27,1444.56 3391.73,1444.56 3409.29,1427 v1(3412,1427)
ISO_Pout_5V0: C23.1 C24.2 C25.1 C29.1 D1:A.1 D2:A.1 R23.2 R29.2 U5.6 | length 241.5
  Bottom w15: v1(3042,2856) 3042.1,2856.1 3068.78,2856.1 U5.6@3068.88,2856.2 ; v1(3137,3291) 3196.5,3291 R29.2@3207.5,3302 ; R23.2@3147.87,2971.69 3142.49,2977.06 C29.1@3142.49,3029.69 3139.31,3029.69 3135,3034 3135,3068.11 3159,3092.11 v1(3159,3094)
  other v1: 3167.87,3135.69 3162,3210
ITCK: U2.100
ITDI: U2.98
ITDO: U2.97
ITMS: U2.99
MCU_A0A1_N: C128.1 R173.1 U1.P2 | length 1830.9
  Top Layer w4.9: C128.1@2009.15,1839.38 2015.06,1833.47 v1(2015.06,1740.88) 2015.06,1700.88 R173.1@2010.13,1695.94 ; v2(3224.83,1921.27) 3240.74,1937.18 3268.97,1937.18 U1.P2@3285.09,1921.06
  Signal Layer 3 w4.9: v1(2015.06,1740.88) 1983.06,1708.88 1983.06,1690.47 1966.7,1674.1 1941.49,1674.1 1914.1,1701.49 1914.1,1788.27 2028.45,1902.62 3044.86,1902.62 3045.05,1902.43 3054.32,1902.43 3080.36,1928.47 3089.47,1928.47 3089.52,1928.42 3193.1,1928.42 3193.15,1928.37 3202.12,1928.37 3209.22,1921.27 v2(3224.83,1921.27)
MCU_A0A1_P: C140.1 R172.1 U1.P1 | length 1752.8
  Top Layer w4.9: C140.1@1947.06,1839.38 1947.06,1747.88 v1(1940.06,1740.88) 1940.06,1703.92 R172.1@1948.04,1695.94 ; v2(3201.83,1901.27) 3202.32,1900.78 3233.32,1900.78 U1.P1@3253.6,1921.06
  Signal Layer 3 w4.9: v1(1940.06,1740.88) 1972.06,1708.88 1972.06,1694.88 1962.18,1685 1946,1685 1925,1706 1925,1783.75 2032.97,1891.72 3040.34,1891.72 3040.53,1891.53 3058.84,1891.53 3084.72,1917.42 3188.54,1917.42 3188.59,1917.37 3197.56,1917.37 3201.08,1913.84 3201.08,1902.01 v2(3201.83,1901.27)
MCU_A2A3_N: C129.1 R175.1 U1.N4 | length 2226.6
  Top Layer w4.9: C129.1@2133.34,1839.38 2138,1834.72 v1(2138,1747) 2138,1699.63 R175.1@2134.31,1695.94
  Top Layer w5: v2(3332.34,1936.81) U1.N4@3348.09,1952.55
  Signal Layer 3 w4.9: v1(2138,1747) 2105.9,1714.9 2105.9,1678.49 2078.16,1650.75 2055.78,1650.75 2055.68,1650.65 1926.21,1650.65 1919.77,1657.09 1919.77,1657.24 1894.3,1682.71 1894.3,1809.71 2007,1922.42 2940.2,1922.42 3048.58,2030.8 3196.39,2030.8 3207.97,2042.38 3252.03,2042.38 3271.9,2022.51 3271.9,1964.52 3284.11,1952.31 3316.84,1952.31 v2(3332.34,1936.81)
MCU_A2A3_P: C141.1 R174.1 U1.N3 | length 2131.3
  Top Layer w4.9: C141.1@2071.24,1839.38 2065.06,1833.2 v1(2065.06,1740.88) 2065.06,1702.92 R174.1@2072.04,1695.94
  Top Layer w5: v2(3300.84,1936.81) U1.N3@3316.59,1952.55
  Signal Layer 3 w4.9: v1(2065.06,1740.88) 2095,1710.94 2095,1683 2073.65,1661.65 1930.77,1661.65 1930.77,1661.72 1930.71,1661.72 1905.2,1687.23 1905.2,1805.2 2011.52,1911.52 2944.71,1911.52 3053.1,2019.9 3200.9,2019.9 3212.48,2031.48 3247.52,2031.48 3261,2018 3261,1960 3284.19,1936.81 v2(3300.84,1936.81)
MCU_A4A5_N: C130.1 R177.1 U1.M5 | length 1845.9
  Top Layer w4.9: C130.1@2257.52,1839.38 2254,1835.86 2255.56,1835.86 2255.56,1745.56 v1(2254,1744) 2254,1700.44 R177.1@2258.49,1695.94
  Top Layer w5: v2(3363.83,1968.3) U1.M5@3379.58,1984.05
  Signal Layer 3 w4.9: v1(2254,1744) 2247.13,1744 2226.41,1723.28 2226.41,1693.18 2250.59,1669 3040,1669 3067.95,1696.95 3447.55,1696.95 3496.8,1746.21 3496.8,1804.04 3485.9,1814.94 3485.9,1815.08 3471.34,1829.65 3439.13,1829.65 3380.93,1887.85 3380.93,1928.07 3363.98,1945.02 v2@3363.98,1968.3
MCU_A4A5_P: C142.1 R176.1 U1.M4 | length 1946.6
  Top Layer w4.9: C142.1@2195.43,1839.38 2195.43,1800.99 2188,1793.56 v1(2188,1747) 2188,1742.4 2196.4,1734 R176.1@2196.4,1695.94
  Top Layer w5: v2(3332.34,1968.3) U1.M4@3348.09,1984.05
  Signal Layer 3 w4.9: v1(2188,1747) 2192.85,1747 2215.41,1724.44 2215.41,1688.76 2246.08,1658.1 3044.51,1658.1 3072.47,1686.05 3452.06,1686.05 3507.7,1741.7 3507.7,1808.55 3496.8,1819.45 3496.8,1819.6 3475.85,1840.55 3443.65,1840.55 3391.83,1892.36 3391.83,1932.58 3379.28,1945.13 3379.28,1974.7 3374.73,1979.25 3374.73,1979.32 3370.25,1983.8 3347.84,1983.8 v2(3332.34,1968.3)
MCU_A8A9_N: C131.1 R179.1 U1.T7 | length 1244.5
  Top Layer w4.9: v2(3430.33,1782.92) 3430.63,1783.22 3430.63,1807.46 3437.35,1814.18 3437.35,1849.91 3442.57,1855.13 U1.T7@3442.57,1858.07
  Signal Layer 6 w4.9: v1(2477,1735) 2480.27,1731.73 2489.61,1731.73 2506.15,1715.18 2862.66,1715.18 2891.37,1743.89 3036.3,1743.89 3083.04,1790.63 3419.08,1790.63 3426.79,1782.92 v2(3430.33,1782.92)
  Bottom w4.9: v1(2477,1735) v1@2479.23,1737.23 ; R179.1@2505.87,1695.32 2494.75,1706.45 2494.75,1719.49 2479.23,1735 v1@2479.23,1737.23 ; C131.1@2505.88,1838.38 2481.44,1813.92 2481.44,1739.44 v1@2479.23,1737.23
MCU_A8A9_P: C143.1 R178.1 U1.R6 | length 1252.4
  Top Layer w4.9: U1.R6@3411.08,1889.56 3426.45,1874.19 3426.45,1818.7 v2(3413.83,1806.08)
  Signal Layer 6 w4.9: v1(2463.94,1761.12) 2466.17,1758.89 2477.86,1758.89 2510.67,1726.08 2858.15,1726.08 2883.66,1751.6 2886.85,1754.79 3031.79,1754.79 3078.53,1801.53 3405.74,1801.53 3410.29,1806.08 v2(3413.83,1806.08)
  Bottom w4.9: R178.1@2443.78,1695.32 2443.78,1740.97 v1(2463.94,1761.12) 2463.94,1818.25 C143.1@2443.81,1838.38
MCU_A10A11_N: C132.1 R181.1 U1.R8 | length 1196.4
  Top Layer w4.9: v2(3457.83,1790.27) 3459.31,1790.27 3468.1,1799.06 3468.1,1826.17 3457.95,1836.32 3457.95,1871.75 3474.07,1887.87 U1.R8@3474.07,1889.56
  Signal Layer 3 w4.9: v1(2607.31,1777.88) 2607.31,1743.13 2616.54,1733.9 3411.71,1733.9 3455.84,1778.03 3455.84,1788.27 v2(3457.83,1790.27)
  Bottom w4.9: C132.1@2630.05,1839.38 2630.06,1816.17 2607.31,1793.42 v1(2607.31,1777.88) 2607.31,1742.36 2631.04,1718.63 R181.1@2631.04,1695.94
MCU_A10A11_P: C144.1 R180.1 U1.T8 | length 1227.9
  Top Layer w4.9: v2(3470.56,1770.91) 3472.1,1772.45 3472.1,1782.69 3479,1789.59 3479,1830.69 3468.85,1840.84 3468.85,1849.91 3474.07,1855.13 U1.T8@3474.07,1858.07
  Signal Layer 3 w4.9: v1(2591.31,1802.88) 2589.31,1800.88 2589.31,1745.72 2596.41,1738.62 2612.03,1723 3416.22,1723 3461.62,1768.4 3468.06,1768.4 v2(3470.56,1770.91)
  Bottom w4.9: R180.1@2567.96,1695.32 2567.96,1746.07 2588.31,1766.42 2588.31,1799.88 v1(2591.31,1802.88) 2591.31,1815.06 C144.1@2567.97,1838.38
MCU_A14B14C14A15B15C15_N: C133.1 R183.1 U1.R2 | length 1664.5
  Top Layer w4.9: C133.1@2382.06,1839.38 2382.06,1816.69 2369,1803.63 v1(2369,1743) 2369,1731.8 2382.67,1718.13 R183.1@2382.67,1695.94
  Top Layer w5: U1.R2@3285.09,1889.56 v2(3300.84,1873.81)
  Signal Layer 6 w4.9: v1(2369,1743) 2346.7,1720.7 2346.7,1703.3 2356,1694 2861.8,1694 2895.57,1727.77 3349.76,1727.77 3349.81,1727.72 3478.17,1727.72 3488,1737.55 3488,1785.68 3395.32,1878.36 3308.94,1878.36 3304.39,1873.81 v2(3300.84,1873.81)
MCU_A14B14C14A15B15C15_P: C145.1 R182.1 U1.R1 | length 1759.7
  Top Layer w4.9: C145.1@2320.06,1839.38 2320.06,1761.06 v1(2318,1759) 2320.58,1756.42 R182.1@2320.58,1695.94
  Top Layer w5: U1.R1@3253.6,1889.56 v2(3269.35,1873.81)
  Signal Layer 6 w4.9: v1(2318,1759) 2318,1742 2335.8,1724.2 2335.8,1698.79 2351.49,1683.1 2866.31,1683.1 2900.08,1716.87 3345.25,1716.87 3345.3,1716.82 3482.68,1716.82 3498.9,1733.03 3498.9,1790.2 3399.84,1889.26 3284.8,1889.26 v2(3269.35,1873.81)
MCU_B0B1_N: C134.1 R185.1 U1.T3 | length 1580.4
  Top Layer w5: v2(3300.84,1842.32) U1.T3@3316.59,1858.07
  Signal Layer 3 w5: v1(1990.06,1768.88) 1992.05,1770.86 1992.05,1783.05 2080.77,1871.77 3032.08,1871.77 3093.78,1810.07 3268.59,1810.07 v2(3300.84,1842.32)
  Bottom w4.9: C134.1@2009.15,1838.38 2009.17,1815.69 1990.06,1796.59 v1(1990.06,1768.88) 1990.06,1738.69 2010.13,1718.63 R185.1@2010.13,1695.94
MCU_B0B1_P: C146.1 R184.1 U1.T2 | length 1561.7
  Top Layer w5: v2(3269.35,1842.32) U1.T2@3285.09,1858.07
  Signal Layer 3 w5: v1(1967.06,1787.88) 1970.32,1791.13 1972.09,1789.36 1982.8,1789.36 2076.21,1882.77 3036.64,1882.77 3098.34,1821.07 3253.85,1821.07 3269.35,1836.57 v2(3269.35,1842.32)
  Bottom w4.9: C146.1@1947.06,1838.38 1947.08,1815.69 1967.06,1795.71 v1(1967.06,1787.88) 1967.06,1737.66 1948.04,1718.63 R184.1@1948.04,1695.94
MCU_B2B3_N: C135.1 R187.1 U1.P3 | length 1547
  Top Layer w5: v2(3300.84,1905.31) U1.P3@3316.59,1921.06
  Signal Layer 3 w4.9: v1(2118.23,1789.7) 2121.01,1792.49 2131.74,1792.49 2179.25,1840 2792.51,1840 2873.51,1759 3061.12,1759 3103.24,1801.12 3295.7,1801.12 3316.29,1821.71 3316.29,1891.18 3302.16,1905.31 v2(3300.84,1905.31)
  Bottom w4.9: R187.1@2133.33,1695.32 2133.33,1718.01 2118.23,1733.11 v1(2118.23,1789.7) 2118.23,1800.57 2133.35,1815.69 C135.1@2133.34,1838.38
MCU_B2B3_P: C147.1 R186.1 U1.R3 | length 1596.6
  Top Layer w5: U1.R3@3316.59,1889.56 v2(3332.34,1905.31)
  Signal Layer 3 w4.9: v1(2093.23,1764.7) 2119.37,1764.7 2183.77,1829.1 2788,1829.1 2869,1748.1 3065.64,1748.1 3107.75,1790.22 3300.22,1790.22 3327.19,1817.19 3327.19,1896.62 3332.34,1901.77 v2(3332.34,1905.31)
  Bottom w4.9: R186.1@2071.23,1695.32 2071.23,1717.51 2093.23,1739.5 v1(2093.23,1764.7) 2093.23,1794.23 2071.26,1816.19 C147.1@2071.24,1838.38
MCU_B4B5_N: C136.1 R189.1 U1.N7 | length 1889.8
  Top Layer w5: v2(3426.83,1936.81) U1.N7@3442.57,1952.55
  Signal Layer 6 w4.9: v1(2238.06,1774.88) 2237.94,1774.88 2222.62,1759.55 2222.62,1681.56 2252.91,1651.27 2898.27,1651.27 2924.17,1677.17 3471.76,1677.17 3512.09,1717.5 3512.09,1798.13 3419.33,1890.88 3419.33,1890.95 3413.42,1896.87 3413.35,1896.87 3411.33,1898.89 3411.33,1921.31 v2(3426.83,1936.81)
  Bottom w4.9: R189.1@2257.51,1695.32 2224,1728.83 2224,1758.36 2238.06,1772.42 2238.06,1796.22 2257.53,1815.69 C136.1@2257.52,1838.38
MCU_B4B5_P: C148.1 R188.1 U1.P7 | length 1880.7
  Top Layer w5: v2(3426.83,1905.31) U1.P7@3442.57,1921.06
  Signal Layer 6 w4.9: v1(2210.06,1790.88) 2211.72,1789.22 2211.72,1677.04 2248.39,1640.37 2902.78,1640.37 2928.68,1666.27 3476.28,1666.27 3522.99,1712.98 3522.99,1802.64 3430.23,1895.4 3430.23,1895.47 3429.33,1896.37 3429.33,1902.8 v2(3426.83,1905.31)
  Bottom w4.9: R188.1@2195.42,1695.32 2210.06,1709.97 v1(2210.06,1790.88) 2210.06,1801.07 2195.44,1815.69 C148.1@2195.43,1838.38
MCU_C2C3_N: C137.1 R191.1 U1.L5 | length 1236.7
  Top Layer w4.9: C137.1@2505.88,1839.38 2502,1835.5 v1(2502,1794) 2501.4,1793.4 2501.4,1701.4 R191.1@2506.85,1695.94
  Top Layer w5: v2(3363.83,1999.8) U1.L5@3379.58,2015.55
  Signal Layer 6 w5: v1(2502,1794) 2479.64,1816.36 2479.64,1827.33 2501.31,1849 2833.59,1849 2838.86,1849 3057.04,2067.19 3199.94,2067.19 3255.88,2011.25 3282.83,1984.3 3348.33,1984.3 v2(3363.83,1999.8)
MCU_C2C3_P: C149.1 R190.1 U1.L4 | length 1231.2
  Top Layer w4.9: C149.1@2443.79,1839.38 2443.79,1807.04 v1(2429.63,1792.88) 2444.76,1777.74 R190.1@2444.76,1695.94
  Top Layer w5: v2(3332.34,1999.8) U1.L4@3348.09,2015.55
  Signal Layer 6 w5: v1(2429.63,1792.88) 2496.75,1860 2833.59,1860 3049.41,2075.82 3050.12,2075.82 3052.48,2078.19 3204.5,2078.19 3263.66,2019.03 3313.11,2019.03 v2(3332.34,1999.8)
MCU_C4: C150.1 R192.1 U1.M6 | length 1519.7
  Top Layer w5: v2(3395.33,1968.3) U1.M6@3411.08,1984.05
  Signal Layer 6 w5: v1(2347,1794) 2446.77,1893.77 2820.26,1893.77 3063.26,2136.77 3234.35,2136.77 3291.46,2079.66 3368.89,2079.66 3379.33,2069.21 3379.33,1984.3 v2(3395.33,1968.3)
  Bottom w5: R192.1@2381.69,1695.32 2381.69,1719.69 2394.5,1732.5 2394.5,1755.42 2359.17,1790.75 2350.25,1790.75 v1(2347,1794) 2367.12,1814.12 2367.12,1823.79 C150.1@2381.72,1838.38
MCU_C6: C138.1 R193.1 U1.K5 | length 1403.4
  Top Layer w5: v2(3363.83,2031.29) U1.K5@3379.58,2047.04
  Signal Layer 6 w5: v1(2349.45,1767) 2467.22,1884.77 2823.99,1884.77 3066.99,2127.77 3230.62,2127.77 3287.73,2070.66 3326.09,2070.66 3363.83,2032.92 v2(3363.83,2031.29)
  Bottom w5: R193.1@2319.6,1695.32 2319.6,1696.31 2335.8,1712.51 2335.8,1714.37 2336.86,1715.44 2336.86,1754.41 v1(2349.45,1767) 2346.88,1769.57 2335.86,1769.57 2317,1788.44 2317,1835.76 C138.1@2319.61,1838.38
